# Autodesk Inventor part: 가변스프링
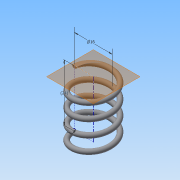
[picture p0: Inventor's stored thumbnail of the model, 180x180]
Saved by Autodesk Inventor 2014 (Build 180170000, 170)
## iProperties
Created: 2015-04
Part Number: 가변스프링
Material: Generic
Document SubType Name: Modeling
Designer: Administrator
Density: 1 g/cm^3
Appearance: Default
Mass: 0.606913 g
Surface Area: 12.5215 cm^2
Volume: 0.606913 cm^3
Author: Administrator
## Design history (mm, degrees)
sketch "스케치1"
  geometry: L1 (0, 0)-(-8, 0); L2 (-8, 0)-(-8, 11.5); L3 (-8, 11.5)-(0, 11.5); L4 (0, 11.5)-(0, 0); C1 r 1 at (-8, 0)
  constraints: 8 end point, 2 parallel, 1 centre point, 1 coincident, 1 horizontal, 1 perpendicular
  dimensions: "d5" = 16 diameter of L2 L4; "d6" = 11.50049 distance between parallel lines of L1 L3 (derived); "d7" = 2 diameter of C1
feature "코일1" pitch "d8" = 10; turns "d10" = 4; dims "d9" = 11.50049 (= d6), "d11" = 0, angle "d12" = 90 deg, angle "d13" = 90 deg, "d14" = 0, "d15" = 0
sketch "스케치2"
  geometry: L1 (9, 0)-(7, 0) reference; 1 further point
  constraints: 1 horizontal alignment
extrude "돌출1" cut sketch "스케치2" stored distance "d16" = 10; taper "d17" = 0 deg
node "작업 평면1"
sketch "스케치3"
  geometry: L1 (7, 0)-(9, 0) reference; 1 further point
  constraints: 1 horizontal alignment
extrude "돌출2" cut sketch "스케치3" stored distance "d18" = 10; taper "d19" = 0 deg
node "솔리드1"
node "절단 모서리 투영1"
node "절단 모서리 투영2"
